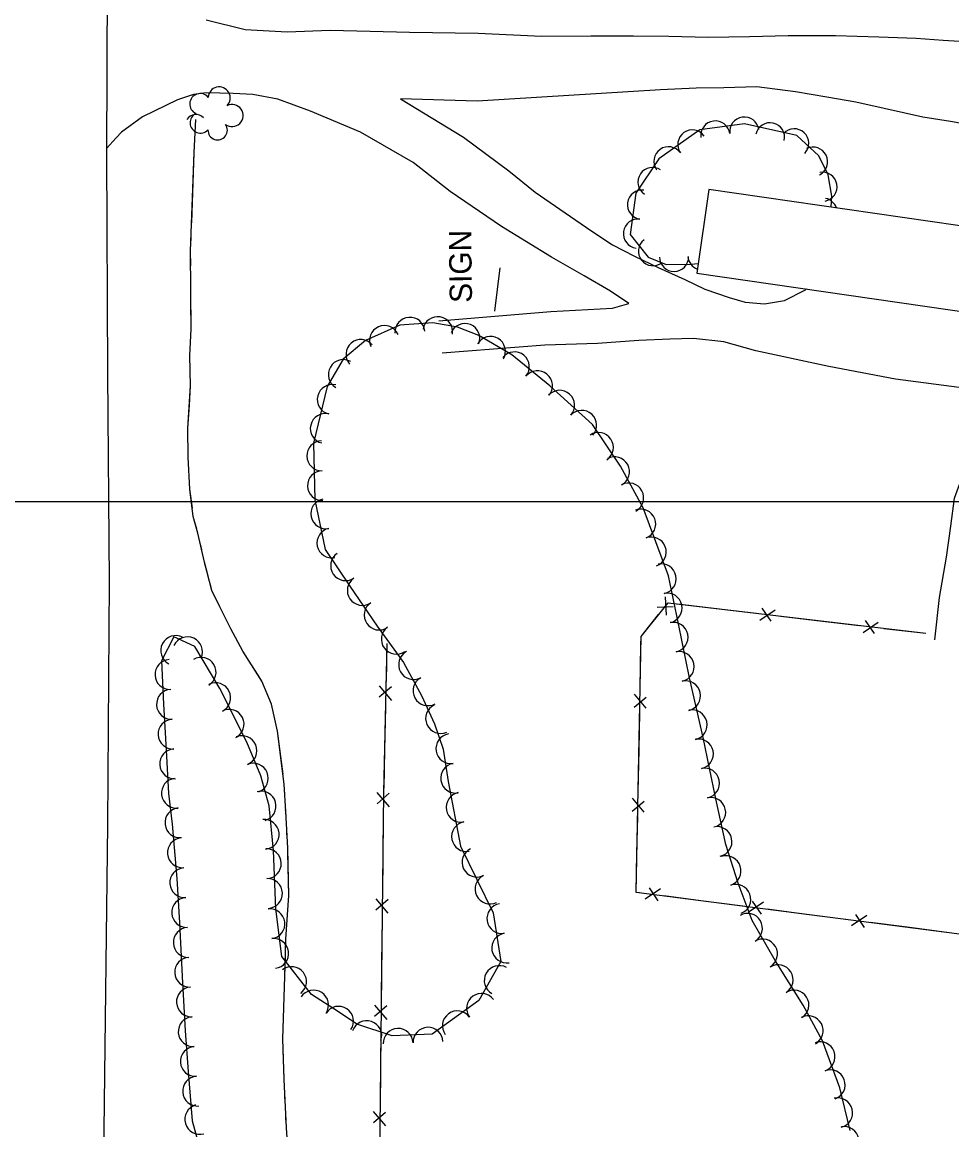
# Model space of a CAD drawing. Extents: x 353423 to 364002, y 127000 to 201942.
# Drawn here: x 362593.6 to 362843.4, y 129831.1 to 130128.8 of the extents above; entities that cross this region are included whole.
import ezdxf

# ---------------------------------------------------------------- set-up
doc = ezdxf.new("R2010")
doc.units = 0
for name, color, linetype in [('E_DTM_SlopeBottom', 7, 'Continuous'), ('E_DTM_SlopeTop', 7, 'Continuous'), ('E_FEN_Generic', 7, 'Continuous'), ('E_LAND_BrushLine', 7, 'Continuous'), ('E_LAND_TreeLine', 7, 'Continuous'), ('E_MISCPROP', 7, 'Continuous'), ('E_STRUCT_WingWall', 7, 'Continuous'), ('E_WTR_FlowLine', 7, 'Continuous')]:
    doc.layers.add(name, color=color, linetype=linetype)

msp = doc.modelspace()

# ---------------------------------------------------------------- linework, layer by layer
at = {"layer": 'E_DTM_SlopeBottom'}
for p, q in [((362766.69, 129969.4), (362766.46, 129974.34)), ((362764.25, 129971.55), (362768.48, 129971.77)), ((362791.79, 129968.07), (362795.88, 129970.86)), ((362792.34, 129971.28), (362794.75, 129967.79)), ((362819.54, 129964.77), (362823.63, 129967.56)), ((362820.1, 129967.98), (362822.51, 129964.49)), ((362689.54, 129950.39), (362692.78, 129946.5)), ((362692.86, 129950.14), (362689.54, 129947.34)), ((362758.04, 129944.63), (362761.27, 129947.37)), ((362761.28, 129944.39), (362758.11, 129948.18)), ((362688.9, 129921.77), (362692.18, 129917.92)), ((362692.23, 129921.56), (362688.94, 129918.72)), ((362760.75, 129916.45), (362757.57, 129920.24)), ((362757.5, 129916.68), (362760.74, 129919.43)), ((362764.52, 129892.6), (362762.14, 129896.11)), ((362688.58, 129893.16), (362691.86, 129889.31)), ((362765.1, 129895.8), (362760.99, 129893.05)), ((362691.9, 129892.95), (362688.61, 129890.12)), ((362792.82, 129892.23), (362788.71, 129889.48)), ((362792.24, 129889.03), (362789.86, 129892.54)), ((362820.54, 129888.66), (362816.43, 129885.91)), ((362819.96, 129885.46), (362817.58, 129888.97)), ((362688.25, 129864.56), (362691.53, 129860.7)), ((362691.58, 129864.35), (362688.29, 129861.51)), ((362687.93, 129835.95), (362691.21, 129832.1)), ((362691.25, 129835.74), (362687.96, 129832.91))]:
    msp.add_line(p, q, dxfattribs=at)
for points in [[(362852.38, 129974), (362849.71, 129962.75), (362896.39, 129957.41), (362976.45, 129948.39), (362975.35, 129925.2), (362973.5, 129867.48), (362885.04, 129878.59), (362758.59, 129894.88), (362759.91, 129963.66), (362767.13, 129972.76), (362836.43, 129964.52)], [(362769.64, 129972.47), (362780.92, 129971.12)], [(362780.92, 129971.12), (362790.84, 129969.95)], [(362759.86, 129961.22), (362759.91, 129963.66), (362764.6, 129969.57)], [(362797.4, 129969.16), (362808.67, 129967.82)], [(362808.67, 129967.82), (362818.59, 129966.64)], [(362825.15, 129965.86), (362836.43, 129964.52)], [(362691.58, 129961.76), (362690.69, 129921.74), (362689.2, 129790.78), (362689.24, 129675.71)], [(362691.58, 129961.76), (362691.35, 129951.54)], [(362759.64, 129949.87), (362759.86, 129961.22)], [(362691.2, 129944.78), (362690.94, 129933.16)], [(362759.33, 129933.28), (362759.52, 129943.26)], [(362690.94, 129933.16), (362690.72, 129922.94)], [(362759.11, 129921.92), (362759.33, 129933.28)], [(362690.62, 129916.18), (362690.49, 129904.56)], [(362758.79, 129905.33), (362758.98, 129915.32)], [(362759.48, 129894.76), (362758.59, 129894.88), (362758.79, 129905.33)], [(362690.49, 129904.56), (362690.38, 129894.34)], [(362775.94, 129892.64), (362766.03, 129893.92)], [(362787.21, 129891.19), (362775.94, 129892.64)], [(362803.66, 129889.07), (362793.76, 129890.35)], [(362690.3, 129887.58), (362690.17, 129875.95)], [(362814.93, 129887.62), (362803.66, 129889.07)], [(362831.38, 129885.5), (362821.48, 129886.78)], [(362842.65, 129884.05), (362831.38, 129885.5)], [(362690.17, 129875.95), (362690.05, 129865.73)], [(362689.97, 129858.97), (362689.84, 129847.35)], [(362689.84, 129847.35), (362689.73, 129837.12)]]:
    msp.add_lwpolyline(points, dxfattribs=at)
msp.add_arc((362640.2, 130101.22), 2.77, 42.0645, 148.3041, dxfattribs=at)
at = {"layer": 'E_DTM_SlopeTop'}
msp.add_lwpolyline([(362613.13, 130780.96), (362611.5, 130718.85), (362611.33, 130635), (362611.94, 130567.59), (362612.57, 130512.06), (362613.33, 130427.49), (362613.97, 130364.73), (362614.38, 130315.44), (362614.9, 130255.36), (362615.3, 130204.37), (362616.47, 130162.51), (362616.24, 130093.34), (362616.51, 130034.34), (362616.94, 129978.49), (362616.48, 129913.07), (362615.49, 129830.98), (362614.36, 129768.53), (362611.97, 129685.25), (362610.4, 129596.8), (362608.43, 129493.57), (362607.54, 129370.88), (362607.83, 129339.32)], dxfattribs=at)
msp.add_lwpolyline([(362613.13, 130780.96), (362611.5, 130718.85), (362611.33, 130635), (362611.94, 130567.59), (362612.57, 130512.06), (362613.33, 130427.49), (362613.97, 130364.73), (362614.38, 130315.44), (362614.9, 130255.36), (362615.3, 130204.37), (362616.47, 130162.51), (362616.24, 130093.34), (362616.51, 130034.34), (362616.94, 129978.49), (362616.48, 129913.07), (362615.49, 129830.98), (362614.36, 129768.53), (362611.97, 129685.25), (362610.4, 129596.8), (362608.43, 129493.57), (362607.54, 129370.88), (362607.83, 129339.32)], dxfattribs=at)
at = {"layer": 'E_FEN_Generic'}
for points in [[(362810.99, 130079.08), (362811.18, 130082), (362810.14, 130087.8), (362807.62, 130092.87), (362801.77, 130098.34), (362787.68, 130101.47), (362775.66, 130099.84), (362764.67, 130092.08), (362758.48, 130082.86), (362756.97, 130071.76), (362761.78, 130065.61), (362766.63, 130063.64), (362773.28, 130063.73), (362775.22, 130063.93)], [(362816.04, 129830.85), (362813.26, 129842.31), (362808.67, 129855.01), (362803.46, 129864.59), (362795.96, 129876.6), (362789.7, 129887.35), (362786.02, 129897.35), (362782.64, 129907.74), (362779.96, 129920.06), (362776.53, 129936.55), (362772.91, 129952.58), (362769.9, 129967.1), (362767.29, 129979.98), (362760.43, 129998.22), (362754.34, 130009.47), (362746.84, 130020.65), (362735.4, 130031.03), (362725.19, 130039.41), (362716.33, 130044.55), (362710.6, 130046.83), (362703.91, 130047.98), (362695.1, 130047.37), (362685.81, 130043.27), (362679.82, 130038.21), (362675.55, 130030.86), (362671.89, 130015.6), (362672.23, 130000.37), (362675.01, 129987.06), (362681.66, 129977.18), (362688.99, 129966.43), (362696.05, 129956.64), (362700.92, 129947.8), (362704.36, 129940.17), (362706.66, 129933.39), (362708.06, 129924.72), (362711.33, 129907.32), (362720.1, 129889.4), (362722.24, 129876.35), (362716.33, 129865.81), (362703.79, 129856.75), (362692.97, 129856.34), (362683.54, 129859.47), (362678.55, 129862.79), (362671.31, 129867.47), (362663.39, 129877.61), (362661.77, 129890.48), (362661.14, 129906.15), (362659.95, 129918.12), (362657.7, 129926.17), (362653.95, 129935.28), (362646.7, 129949.65), (362640.01, 129960.96), (362634.35, 129963.57), (362630.97, 129957.1), (362631.58, 129945.45), (362632.24, 129933.14), (362632.91, 129921.47), (362633.89, 129913.18), (362635.09, 129898.59), (362635.86, 129886.7), (362636.53, 129872.27), (362637.41, 129857.7), (362638.19, 129846.76), (362639.22, 129833.46), (362642.25, 129822.83)]]:
    msp.add_lwpolyline(points, dxfattribs=at)
for centre, radius, start, end in [((362646.51, 130108.42), 2.97, 315.8302, 177.0641), ((362641.38, 130106.83), 2.78, 38.8011, 246.5741), ((362649.98, 130103.7), 2.97, 233.481, 116.4543), ((362641.47, 130101.77), 2.78, 115.4781, 316.4891), ((362779.84, 130098.33), 3.92, 7.7616, 187.7462), ((362787.61, 130099.39), 3.92, 7.7616, 187.7462), ((362794.55, 130097.84), 3.92, 347.4664, 167.4511), ((362646.1, 130099.77), 2.61, 178.1862, 36.1188), ((362773.66, 130095.91), 3.92, 35.2146, 215.1993), ((362801.03, 130096.22), 3.92, 316.9306, 136.9153), ((362767.25, 130091.39), 3.92, 35.2146, 215.1993), ((362806.11, 130091.3), 3.92, 296.369, 116.3537), ((362762.96, 130085.84), 3.92, 56.1387, 236.1234), ((362808.63, 130084.57), 3.92, 280.2281, 100.2128), ((362760.13, 130079.74), 3.92, 82.2112, 262.1958), ((362808.7, 130077.56), 3.92, 19.6087, 78.8761), ((362759.06, 130071.97), 3.92, 82.2112, 262.1958), ((362763.11, 130067.24), 3.92, 128.0743, 308.059), ((362768.74, 130065.72), 3.92, 180.8526, 0.8373), ((362776.39, 130066.12), 3.92, 185.8502, 249.3873), ((362697.76, 130045.45), 4.01, 3.9749, 183.9596), ((362705.24, 130045.62), 4.01, 350.1986, 170.1833), ((362690.91, 130043.23), 4.01, 23.8356, 203.8203), ((362712.56, 130043.79), 4.01, 338.3307, 158.3154), ((362684.59, 130039.49), 4.01, 40.1886, 220.1733), ((362719.43, 130040.33), 4.01, 329.8889, 149.8736), ((362725.85, 130036.15), 4.01, 320.6118, 140.5965), ((362679.85, 130034.09), 4.01, 59.8672, 239.8519), ((362732.05, 130031.06), 4.01, 320.6118, 140.5965), ((362676.88, 130027.38), 4.01, 76.5097, 256.4943), ((362738, 130025.84), 4.01, 317.7914, 137.776), ((362743.94, 130020.45), 4.01, 317.7914, 137.776), ((362675.01, 130019.58), 4.01, 76.5097, 256.4943), ((362748.44, 130014.49), 4.01, 303.8666, 123.8512), ((362674.06, 130012.22), 4.01, 91.2679, 271.2526), ((362752.76, 130007.97), 4.01, 298.4476, 118.4323), ((362674.24, 130004.2), 4.01, 91.2679, 271.2526), ((362756.58, 130000.92), 4.01, 298.4476, 118.4323), ((362675.15, 129996.66), 4.01, 101.844, 281.8287), ((362759.81, 129993.91), 4.01, 290.6095, 110.5942), ((362676.79, 129988.81), 4.01, 101.844, 281.8287), ((362762.63, 129986.4), 4.01, 290.6095, 110.5942), ((362680.49, 129982.69), 4.01, 123.9364, 303.9211), ((362765.31, 129979.19), 4.01, 281.4809, 101.4656), ((362684.97, 129976.05), 4.01, 124.2818, 304.2665), ((362766.9, 129971.33), 4.01, 281.4809, 101.4656), ((362689.49, 129969.43), 4.01, 124.2818, 304.2665), ((362694.1, 129962.93), 4.01, 125.8267, 305.8114), ((362768.51, 129963.46), 4.01, 281.7026, 101.6873), ((362634.81, 129959.9), 4.01, 62.4028, 242.3875), ((362638.01, 129959.57), 4.01, 335.3224, 155.3071), ((362698.75, 129956.1), 4.01, 118.8294, 298.8141), ((362770.14, 129955.61), 4.01, 281.7026, 101.6873), ((362633.27, 129953.45), 4.01, 92.9902, 272.9749), ((362641.66, 129954.06), 4.01, 300.5923, 120.577), ((362645.57, 129947.22), 4.01, 296.7669, 116.7516), ((362702.62, 129949.07), 4.01, 118.8294, 298.8141), ((362771.85, 129947.73), 4.01, 282.721, 102.7057), ((362633.68, 129945.44), 4.01, 93.0756, 273.0603), ((362649.18, 129940.06), 4.01, 296.7669, 116.7516), ((362706.01, 129941.62), 4.01, 114.3084, 294.2931), ((362773.62, 129939.91), 4.01, 282.721, 102.7057), ((362634.11, 129937.43), 4.01, 93.0756, 273.0603), ((362652.62, 129932.99), 4.01, 292.4055, 112.3902), ((362708.77, 129933.51), 4.01, 99.2095, 279.1941), ((362775.31, 129932.1), 4.01, 281.7611, 101.7458), ((362634.55, 129929.43), 4.01, 93.2702, 273.2549), ((362655.68, 129925.58), 4.01, 292.4055, 112.3902), ((362710.05, 129925.59), 4.01, 99.2095, 279.1941), ((362776.94, 129924.25), 4.01, 281.7611, 101.7458), ((362635.01, 129921.55), 4.01, 96.7728, 276.7575), ((362657.77, 129918.09), 4.01, 285.5974, 105.5821), ((362711.51, 129917.75), 4.01, 100.648, 280.6327), ((362778.61, 129916.38), 4.01, 282.2773, 102.2619), ((362635.95, 129913.59), 4.01, 96.7728, 276.7575), ((362658.6, 129910.48), 4.01, 275.7121, 95.6968), ((362712.99, 129909.87), 4.01, 100.648, 280.6327), ((362780.31, 129908.54), 4.01, 282.2773, 102.2619), ((362636.62, 129905.52), 4.01, 94.7014, 274.6861), ((362659.18, 129902.61), 4.01, 272.2918, 92.2765), ((362715.78, 129903.01), 4.01, 116.0806, 296.0653), ((362782.73, 129900.68), 4.01, 288.0426, 108.0273), ((362637.26, 129897.48), 4.01, 93.7229, 273.7076), ((362719.3, 129895.81), 4.01, 116.0806, 296.0653), ((362659.5, 129894.6), 4.01, 272.2918, 92.2765), ((362785.37, 129893.02), 4.01, 290.224, 110.2087), ((362637.78, 129889.48), 4.01, 93.7229, 273.7076), ((362660.16, 129886.43), 4.01, 277.1929, 97.1776), ((362722.48, 129887.85), 4.01, 99.3461, 279.3308), ((362788.49, 129885.25), 4.01, 300.2246, 120.2093), ((362638.21, 129881.43), 4.01, 92.6861, 272.6707), ((362661.17, 129878.47), 4.01, 277.1929, 97.1776), ((362723.78, 129879.93), 4.01, 99.3461, 279.3308), ((362792.53, 129878.32), 4.01, 300.2246, 120.2093), ((362638.58, 129873.42), 4.01, 92.6861, 272.6707), ((362796.73, 129871.41), 4.01, 301.998, 121.9827), ((362665.98, 129870.89), 4.01, 307.9959, 127.9805), ((362721.76, 129871.19), 4.01, 60.7256, 240.7103), ((362639.05, 129865.44), 4.01, 93.4366, 273.4213), ((362671.89, 129864.59), 4.01, 327.1569, 147.1416), ((362717.02, 129863.71), 4.01, 35.8376, 215.8223), ((362800.98, 129864.61), 4.01, 301.998, 121.9827), ((362678.59, 129860.24), 4.01, 326.3679, 146.3526), ((362639.53, 129857.45), 4.01, 94.0821, 274.0668), ((362686.18, 129856.38), 4.01, 341.6347, 161.6194), ((362710.51, 129859.02), 4.01, 35.8376, 215.8223), ((362804.81, 129857.71), 4.01, 298.5212, 118.5059), ((362694.61, 129854.3), 4.01, 2.1826, 182.1673), ((362702.63, 129854.61), 4.01, 2.1826, 182.1673), ((362807.99, 129850.71), 4.01, 289.8664, 109.8511), ((362640.1, 129849.45), 4.01, 94.0821, 274.0668), ((362810.71, 129843.17), 4.01, 289.8664, 109.8511), ((362640.7, 129841.46), 4.01, 94.4604, 274.4451), ((362812.72, 129835.64), 4.01, 283.681, 103.6657), ((362641.28, 129833.88), 4.01, 105.9203, 285.905), ((362814.45, 129827.93), 4.01, 280.4908, 100.4755)]:
    msp.add_arc(centre, radius, start, end, dxfattribs=at)
at = {"layer": 'E_LAND_BrushLine'}
msp.add_line((362720.58, 130051.14), (362722.03, 130062.76), dxfattribs=at)
at = {"layer": 'E_LAND_TreeLine'}
msp.add_line((360000, 130000), (363500, 130000), dxfattribs=at)
at = {"layer": 'E_MISCPROP'}
for points in [[(362643.04, 130129.42), (362653.51, 130126.8), (362664.74, 130126.24), (362676.32, 130126.65), (362687.09, 130126.34), (362697.66, 130126.07), (362716.14, 130125.87), (362733.1, 130125), (362746.38, 130125.14), (362757.89, 130125.16), (362767.33, 130125.01), (362777.9, 130124.78), (362789.03, 130124.97), (362799.39, 130125.21), (362812.14, 130125.21), (362823.79, 130124.88), (362833.84, 130124.47), (362841.05, 130123.97), (362848.41, 130123.53)], [(362765.12, 130110.62), (362715.87, 130107.6), (362695.27, 130108.2)], [(362850.53, 130100.79), (362843.05, 130102.06), (362835.61, 130103.24), (362825.24, 130105.59), (362817.62, 130107.29), (362809.83, 130108.64), (362801.37, 130110.09), (362790.98, 130111.38), (362782.17, 130111.15), (362774.68, 130111.04), (362765.12, 130110.62)], [(362705.51, 130048.56), (362735.68, 130051), (362752.23, 130051.96), (362756.64, 130053.2), (362751.7, 130056.47), (362744.57, 130060.6), (362735.83, 130065.65), (362722.35, 130073.86), (362708.59, 130083.3), (362698.66, 130091.12), (362684.5, 130099.2), (362671.02, 130104.84), (362662.31, 130108.11), (362655.52, 130109.34), (362650.25, 130109.59), (362643.09, 130109.85), (362639.61, 130109.4), (362635.34, 130107.96), (362625.92, 130103.32), (362620.22, 130099.25), (362618.87, 130097.73), (362616.25, 130094.87)], [(362695.27, 130108.2), (362712.18, 130097.93), (362724.35, 130088.87), (362731.45, 130083.12), (362739.52, 130077.56), (362746.69, 130072.58), (362752.18, 130068.99), (362758.11, 130065.87), (362764.46, 130062.89), (362771.66, 130059.6), (362777.04, 130057.06), (362783.52, 130054.81), (362787.87, 130053.55), (362793.1, 130053.08), (362798.41, 130053.98), (362804.07, 130056.83), (362804.38, 130057.09)], [(362838.79, 129962.73), (362840.12, 129974.18), (362841.96, 129985), (362843.1, 129993.33), (362844.07, 130000.87), (362846.52, 130007.46), (362849.71, 130012.86), (362854.6, 130019.29), (362857.31, 130023.23), (362858.65, 130026.31), (362857.95, 130027.78), (362856.47, 130029.01), (362854.2, 130029.47), (362828.23, 130032.8), (362810.36, 130036.2), (362790.73, 130040.42), (362782.1, 130042.85), (362774.01, 130043.78), (362767.66, 130043.58), (362759.29, 130043.2), (362748.16, 130042.45), (362734.01, 130041.96), (362706.44, 130039.8)]]:
    msp.add_lwpolyline(points, dxfattribs=at)
at = {"layer": 'E_STRUCT_WingWall'}
for points in [[(362665.33, 129821.04), (362664.57, 129831.61), (362663.99, 129844.56), (362663.61, 129855.5), (362664.19, 129872.24), (362664.41, 129882.29), (362665.26, 129894.02), (362664.92, 129906.79), (362664.39, 129916.61), (362664.01, 129924.01), (362662.16, 129938.22), (362660.54, 129945.51), (362658.01, 129951.67), (362655.23, 129956.04), (362652.87, 129959.69), (362649.6, 129965.71), (362646.68, 129971.6), (362644.58, 129976.07), (362642.55, 129983.62), (362640.81, 129991.46), (362639.56, 129995.96), (362638.67, 130003.26), (362638.22, 130011.83), (362638.12, 130019.63), (362638.8, 130031.04), (362638.63, 130039.23), (362638.96, 130046.3), (362638.84, 130067.27), (362639.81, 130093.77), (362640.28, 130102.66)], [(362639.12, 130074.82), (362639.81, 130093.77), (362640.28, 130102.66)], [(362638.91, 130069.06), (362638.98, 130070.98)], [(362638.87, 130063.31), (362638.85, 130065.23)], [(362638.9, 130057.55), (362638.89, 130059.47)], [(362638.5, 130025.89), (362638.8, 130031.04), (362638.63, 130039.23), (362638.96, 130046.3), (362638.92, 130053.71)], [(362639.3, 129998.14), (362638.67, 130003.26), (362638.22, 130011.83), (362638.12, 130019.63), (362638.5, 130025.89)], [(362640.51, 129992.54), (362640, 129994.38)], [(362641.81, 129986.94), (362641.4, 129988.81)], [(362643.16, 129981.35), (362642.66, 129983.2)], [(362656.96, 129953.31), (362655.23, 129956.04), (362652.87, 129959.69), (362649.6, 129965.71), (362646.68, 129971.6), (362644.58, 129976.07), (362644.16, 129977.64)], [(362663.67, 129926.62), (362662.16, 129938.22), (362660.54, 129945.51), (362658.01, 129951.67), (362656.96, 129953.31)], [(362664.17, 129920.89), (362664.07, 129922.8)], [(362664.47, 129915.13), (362664.39, 129916.61), (362664.37, 129917.05)], [(362664.78, 129909.38), (362664.68, 129911.29)], [(362664.3, 129877.72), (362664.41, 129882.29), (362665.26, 129894.02), (362664.95, 129905.54)], [(362663.8, 129849.88), (362663.61, 129855.5), (362664.19, 129872.24), (362664.3, 129877.72)], [(362664.01, 129844.12), (362663.99, 129844.56), (362663.94, 129846.04)], [(362664.27, 129838.37), (362664.18, 129840.29)], [(362664.52, 129832.61), (362664.44, 129834.53)]]:
    msp.add_lwpolyline(points, dxfattribs=at)
at = {"layer": 'E_WTR_FlowLine'}
msp.add_lwpolyline([(362774.85, 130061.35), (362856.59, 130049.54), (362859.84, 130072.02), (362778.1, 130083.83)], close=True, dxfattribs=at)

# ---------------------------------------------------------------- texts
at = {"layer": 'E_LAND_BrushLine'}
msp.add_text('SIGN', height=6, rotation=90.7611, dxfattribs=at).set_placement((362714.48, 130053.39))

doc.saveas('drawing.dxf')
